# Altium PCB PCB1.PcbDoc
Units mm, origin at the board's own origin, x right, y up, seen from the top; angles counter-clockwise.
Board outline 13.5 x 35 mm, 4 copper layers (Top Copper, Signal Layer 1, Signal Layer 2, Bottom Copper), stack 1.57 mm thick; 12 components, 10 nets, 41 pads, 33 vias.
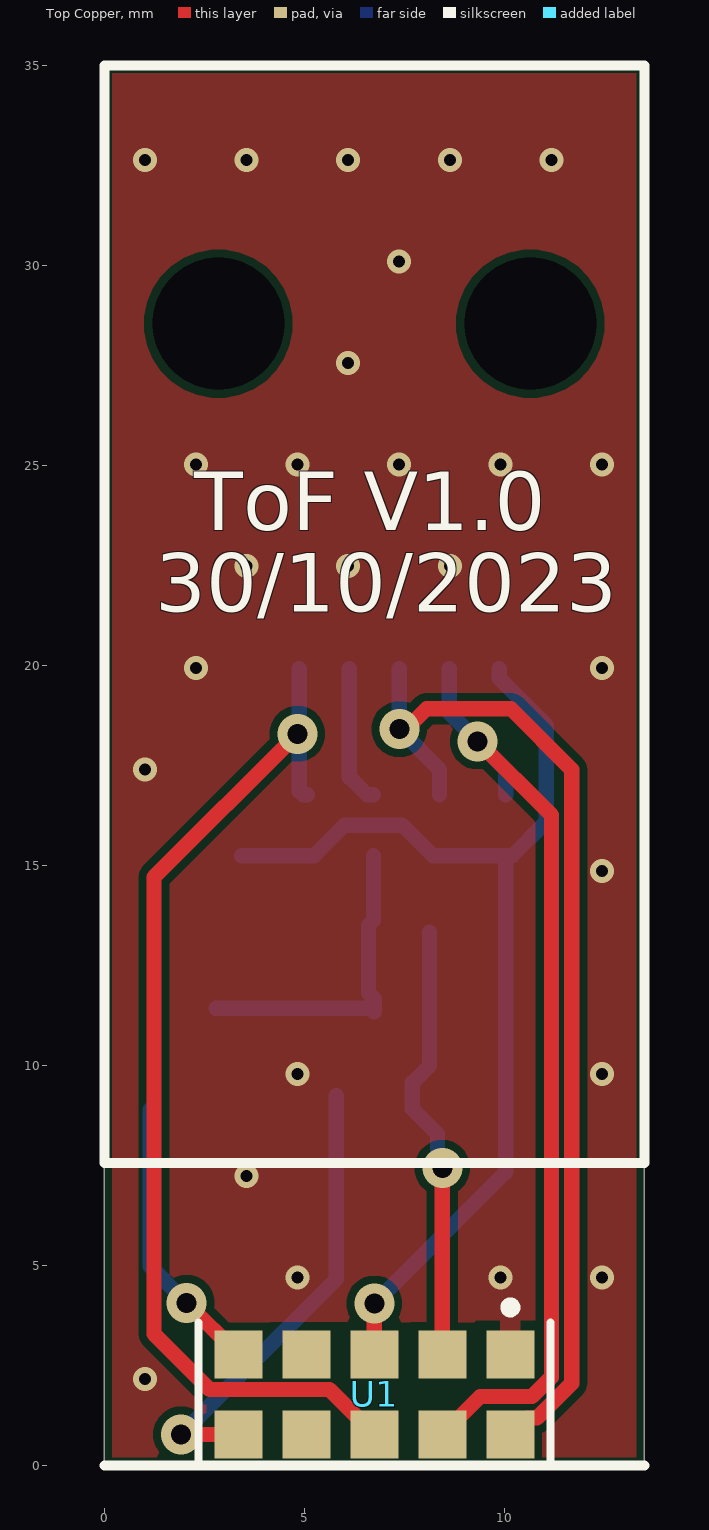
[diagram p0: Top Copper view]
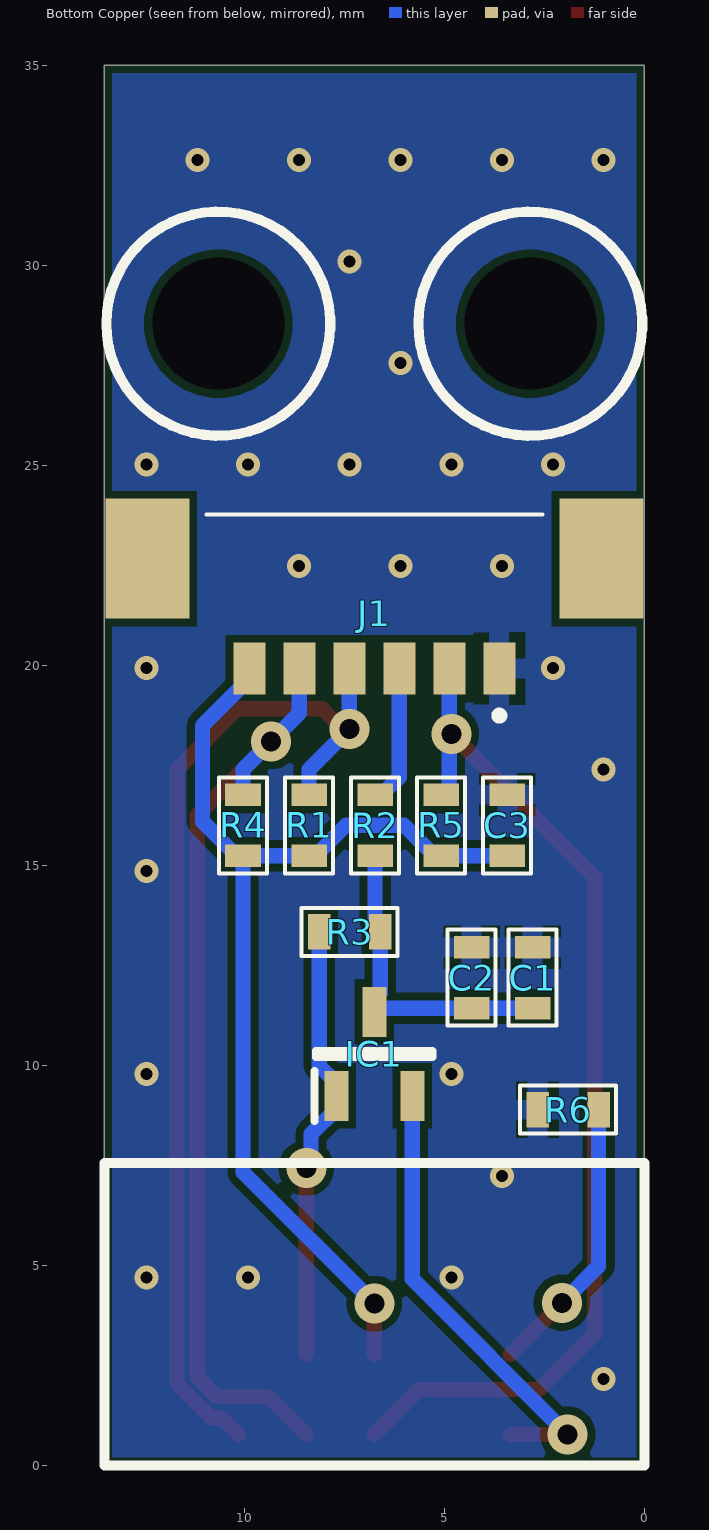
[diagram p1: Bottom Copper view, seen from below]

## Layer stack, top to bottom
Top Mask: solder mask 0.015, Solder Resist, Dk 3.8
Top Copper: signal copper 0.035
Dielectric 1: prepreg 0.2, 7628, Dk 4.6
Signal Layer 1: signal copper 0.0175
Core: core 1.065, FR-4, Dk 4.5
Signal Layer 2: signal copper 0.0175
Dielectric 2: prepreg 0.2, 7628, Dk 4.6
Bottom Copper: signal copper 0.035
Bottom Mask: solder mask 0.015, Solder Resist, Dk 3.8

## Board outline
0,0 0,35 13.5,35 13.5,0

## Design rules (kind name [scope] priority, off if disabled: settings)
BoardOutlineClearance [All] p1: gap=0.2 ignorepadtopadclearanceinfootprint=FALSE except(0.4: Arc-SplitBarrior Arc-SplitContinuation Track-SplitBarrior Track-SplitContinuation SMDPad-SplitBarrior SMDPad-SplitContinuation THPad-SplitBarrior THPad-SplitContinuation Via-SplitBarrior Via-SplitContinuation Fill-SplitBarrior Fill-SplitContinuation Poly-SplitBarrior Poly-SplitContinuation Region-SplitBarrior Region-SplitContinuation Text-SplitBarrior Text-SplitContinuation)
Clearance "Clearance Bottom Layer" [OnLayer('Bottom Layer')] p1: gap=0.203 ignorepadtopadclearanceinfootprint=TRUE except(0.254: Arc-Text Track-Text SMDPad-Text THPad-Text Via-Text Fill-Text Poly-Text Region-Text Text-Text)
Clearance "Clearance Top Layer" [OnLayer('Top Layer')] p2: gap=0.203 ignorepadtopadclearanceinfootprint=TRUE except(0.254: Arc-Text Track-Text SMDPad-Text THPad-Text Via-Text Fill-Text Poly-Text Region-Text Text-Text)
Clearance [All] p3: gap=0.2 ignorepadtopadclearanceinfootprint=FALSE except(0.089: Arc-Arc Arc-Track Arc-SMDPad Track-Track Track-SMDPad SMDPad-SMDPad; 0.127: Arc-Via Track-Via SMDPad-Via THPad-Via Via-Via; 0.254: Arc-Text Track-Text SMDPad-Text THPad-Text Via-Text Fill-Text Poly-Text Region-Text Text-Text)
HoleSize [All] p1: absolutevalues=TRUE maxlimit=6.3 minlimit=0.2 maxpercent=80.000 minpercent=20.000
MinimumAnnularRing [All] p1: minimumring=0.076
MinimumSolderMaskSliver [All] p1: minsoldermaskwidth=0.1
PolygonConnect PolygonConnect_1 [All] p1: thpad.connectstyle=Relief thpad.reliefconductorwidth=0.508 thpad.reliefentries=4 thpad.polygonreliefangle="90 Angle" thpad.airgapwidth=0.254 smdpad.connectstyle=Relief smdpad.reliefconductorwidth=0.508 smdpad.reliefentries=4 smdpad.polygonreliefangle="90 Angle" smdpad.airgapwidth=0.254 via.connectstyle=Direct via.reliefconductorwidth=0.508 via.reliefentries=4 via.polygonreliefangle="90 Angle" via.airgapwidth=0.254
RoutingCorners [All] p1: cornerstyle=Round minsetback=2.54 maxsetback=2.54
RoutingVias [All] p1: holewidth=0.5 width=1 viastyle="Through Hole" minholewidth=0.2 minwidth=0.45 maxholewidth=1 maxwidth=2
SilkToSilkClearance [All] p1: silktosilkclearance=0.1
SilkToSolderMaskClearance [IsPad] p1: minsilkscreentomaskgap=0.1 clearancetoexposedcopper=TRUE
SolderMaskExpansion [All] p1: expansion=0.102 istentingtop=FALSE
Width [All] p1: maxlimit=2.54 minlimit=0.089 preferedwidth=0.381
25 further rules are at their usual default settings.

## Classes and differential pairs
component class main: C1 C2 C3 IC1 J1 R1 R2 R3 R5 R6 U1

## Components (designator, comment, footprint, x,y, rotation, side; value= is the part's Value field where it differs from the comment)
C1 "220µF" CAP_0603_0H80 2.794,12.192 r90 bottom
C2 "220µF" CAP_0603_0H80 4.318,12.192 r90 bottom
C3 "0.1µF" CAP_0603_0H80 3.429,16.002 r270 bottom
IC1 "SI2301BDS-T1-E3" SOT95P237X112-3N 6.75,10.287 r90 bottom
J1 "53398-0671" 533980671 6.75,21.844 r180 bottom
R1 "2.2k" RES_0603_0H90_2 8.382,16.002 r270 bottom
R2 "4.7R" RES_0603_0H90_2 6.731,16.002 r90 bottom
R3 "1k" RES_0603_0H90_2 7.366,13.335 r180 bottom
R4 "2.2k" RES_0603_0H90_2 10.033,16.002 r270 bottom
R5 "8.2k" RES_0603_0H90_2 5.08,16.002 r270 bottom
R6 "2.7R" RES_0603_0H90_2 1.905,8.89 r180 bottom
U1 "VCNL4200" FP-VCNL4200-MFG 6.75,1.773 r180 top

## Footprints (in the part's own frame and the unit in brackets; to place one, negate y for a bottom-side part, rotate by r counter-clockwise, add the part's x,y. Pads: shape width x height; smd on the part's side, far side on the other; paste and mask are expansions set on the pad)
533980671 [mm]
  rect 0.8x1.3 smd: 1(3.125,-1.925) 2(1.875,-1.925) 3(0.625,-1.925) 4(-0.625,-1.925) 5(-1.875,-1.925) 6(-3.125,-1.925)
  rect 2.1x3 smd: MP1(-5.675,0.825) MP2(5.675,0.825)
  silkscreen extent -4.2,-3.2 4.2,1.93, body extent -6.32,-2.54 6.32,1.66, height 4.7
CAP_0603_0H80 [mil] "refusion"
  rect 22x35 smd: 1(-30,0) 2(30,0)
  silkscreen extent -47,-24 47,24, body extent -31,-16 31,16, height 31
FP-VCNL4200-MFG [mm]
  rect 1.2x1.2 smd paste+0 mask+0: 1(-3.4,-1) 2(-1.7,-1) 3(0,-1) 4(1.7,-1) 5(3.4,-1) 6(3.4,1) 7(1.7,1) 8(0,1) 9(-1.7,1) 10(-3.4,1)
  silkscreen extent -4.4,-2.3 4.4,1.8, body extent -4.15,-1.7 4.15,1.7, height 0.25
RES_0603_0H90_2 [mil]
  rect 22x35 smd: 1(-30,0) 2(30,0)
  silkscreen extent -47,-24 47,24, body extent -31,-16 31,16, height 35
SOT95P237X112-3N [mm]
  rect 1.25x0.6 smd: 1(-1.05,0.95) 2(-1.05,-0.95) 3(1.05,0)
  silkscreen extent -1.67,-1.46 0.07,1.5, body extent -1.27,-1.46 1.27,1.46, height 1

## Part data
C1 C2: library part C0603-10µF-X5R-6.3V, "Capacitor, Ceramic, 220µF, 0603, 10%, 6.3V, X5R", CASE=0603, Dielectric=X5R, Voltage=6.3V
C3: library part C0603-10µF-X5R-6.3V, "Capacitor, Ceramic, 0.1µF, 0603, 10%, 6.3V, X5R", CASE=0603, Dielectric=X5R, Voltage=6.3V
IC1: "Integrated Circuit", Manufacturer_Name=Vishay, Mouser Part Number=781-SI2301BDS-E3
J1: "Connector", Manufacturer_Name=Molex, Mouser Part Number=538-53398-0671
R1 R4: library part R0603_120k_1%, "Resistor, Thin Film, 2.2k, 1%, 65mW, 0603", CASE=0603, Power=65mW, Tolerance=1%
R2: library part R0603_120k_1%, "Resistor, Thin Film, 4.7R, 1%, 65mW, 0603", CASE=0603, Power=65mW, Tolerance=1%
R3: library part R0603_120k_1%, "Resistor, Thin Film, 1k, 1%, 65mW, 0603", CASE=0603, Power=65mW, Tolerance=1%
R5: library part R0603_120k_1%, "Resistor, Thin Film, 8.2k, 1%, 65mW, 0603", CASE=0603, Power=65mW, Tolerance=1%
R6: library part R0603_120k_1%, "Resistor, Thin Film, 2.7R, 1%, 65mW, 0603", CASE=0603, Power=65mW, Tolerance=1%
U1: library part CMP-02530-000006-1, "SENSOR OPT 550NM AMBIENT 10SMD", Ambient Temperature Range High=+85°C, Ambient Temperature Range Low=-40°C, Manufacturer=Vishay, Max Supply Voltage=3.6V, Min Supply Voltage=2.5V, Operating Supply Current=350uA, Package=0, Temperature="-40°C to +85°C"

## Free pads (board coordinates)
  round 1.524 hole 3.3 unplated: Pad1(2.85,28.54) Pad2(10.65,28.54)

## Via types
v1: diameter 0.6, hole 0.3, Top Copper to Bottom Copper, tented both sides, 26 vias
v2: diameter 1, hole 0.5, Top Copper to Bottom Copper, tented both sides, 7 vias

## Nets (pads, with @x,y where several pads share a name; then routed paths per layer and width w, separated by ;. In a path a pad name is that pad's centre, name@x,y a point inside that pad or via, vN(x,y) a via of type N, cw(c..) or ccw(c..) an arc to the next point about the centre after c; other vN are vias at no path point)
3V3: C3.2 J1.6 R1.2 R4.2 R5.2 U1.3 | length 26.7
  Top Copper w0.381: U1.3 v2(6.75,4.045)
  Bottom Copper w0.381: C3.2 R5.2 5.245,15.24 6.007,16.002 7.455,16.002 8.217,15.24 R1.2 R4.2 ; v2(6.75,4.045) 10.033,7.328 R4.2 ; J1.6 9.875,19.669 11.049,18.495 11.049,16.091 10.198,15.24 R4.2
5V: J1.3 R2.2 | length 3.5
  Bottom Copper w0.381: J1.3 6.125,17.205 6.566,16.764 R2.2
GND: C1.2 C2.2 C3.1 J1.1 R6.1 U1.1
  other v1: 1.016,2.159 4.826,4.699 9.906,4.699 12.446,4.699 3.556,7.239 4.826,9.779 12.446,9.779 12.446,14.859 1.016,17.399 2.286,19.939 12.446,19.939 3.556,22.479 6.096,22.479 8.636,22.479 2.286,25.019 4.826,25.019 7.366,25.019 9.906,25.019 12.446,25.019 6.096,27.559 7.366,30.099 1.016,32.639 3.556,32.639 6.096,32.639 8.636,32.639 11.176,32.639
INT: J1.2 R5.1 U1.8 | length 26.3
  Top Copper w0.381: v2(4.826,18.288) 1.242,14.704 1.242,3.286 2.634,1.894 5.629,1.894 U1.8
  Bottom Copper w0.381: J1.2 4.875,16.853 4.964,16.764 R5.1
NetC1_1: C1.1 C2.1 IC1.3 R2.1 R3.2 | length 8
  Bottom Copper w0.381: C1.1 C2.1 6.657,11.43 IC1.3 6.75,11.662 6.604,11.808 R3.2 6.604,13.5 6.731,13.627 R2.1
NetIC1_1: IC1.1 R3.1 U1.2 | length 11
  Top Copper w0.381: U1.2 v2(8.45,7.434)
  Bottom Copper w0.381: R3.1 8.128,9.99 7.7,9.562 IC1.1 7.7,8.912 8.332,8.28 8.332,7.552 v2(8.45,7.434)
NetIC1_2: IC1.2 U1.6 | length 11.5
  Top Copper w0.381: v2(1.916,0.773) U1.6
  Bottom Copper w0.381: v2(1.916,0.773) 5.8,4.657 IC1.2
NetR6_2: R6.2 U1.5 | length 7
  Top Copper w0.381: v2(2.059,4.064) U1.5
  Bottom Copper w0.381: R6.2 1.143,4.98 v2(2.059,4.064)
SCL: J1.4 R1.1 U1.10 | length 26.1
  Top Copper w0.381: v2(7.375,18.406) 7.542,18.406 8.051,18.915 10.168,18.915 11.684,17.399 11.684,2.047 10.819,1.183 10.559,1.183 U1.10
  Bottom Copper w0.381: J1.4 v2(7.375,18.406) 8.382,17.399 R1.1
SDA: J1.5 R4.1 U1.9 | length 23.7
  Top Copper w0.381: U1.9 9.398,1.721 10.693,1.721 11.176,2.204 11.176,16.256 v2(9.335,18.098)
  Bottom Copper w0.381: J1.5 8.625,18.807 v2(9.335,18.098) 10.033,17.399 R4.1
pads on no net: J1.MP1 J1.MP2 U1.4 U1.7

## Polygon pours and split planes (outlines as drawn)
GND on Bottom Copper "GND_L04_P000" (solid, pour order 0): -1.905,-0.762 -1.651,-0.508 -1.651,37.719 14.097,37.719 14.605,37.211 14.605,-1.905
GND on Top Copper "GND_L01_P001" (solid, pour order 1): -0.889,-1.524 -0.889,34.29 -1.651,35.052 0.254,36.957 13.843,36.957 14.478,36.322 14.097,35.941 14.097,-0.381

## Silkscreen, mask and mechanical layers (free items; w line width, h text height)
Top Overlay:
  lines w0.254: 0,0 13.5,0 ; 0,7.56 13.5,7.56 13.5,35 0,35 0,7.56
  text "ToF V1.0" at 2.25,22.888 h2.5
  text "30/10/2023" at 1.27,20.856 h2.5
Bottom Overlay:
  circle w0.254: c10.65,28.54 r2.8
  circle w0.254: c2.85,28.54 r2.8
  lines w0.254: 0,0 13.5,0 13.5,7.56 0,7.56 0,0
Mechanical 1:
  the board outline again, w0.254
